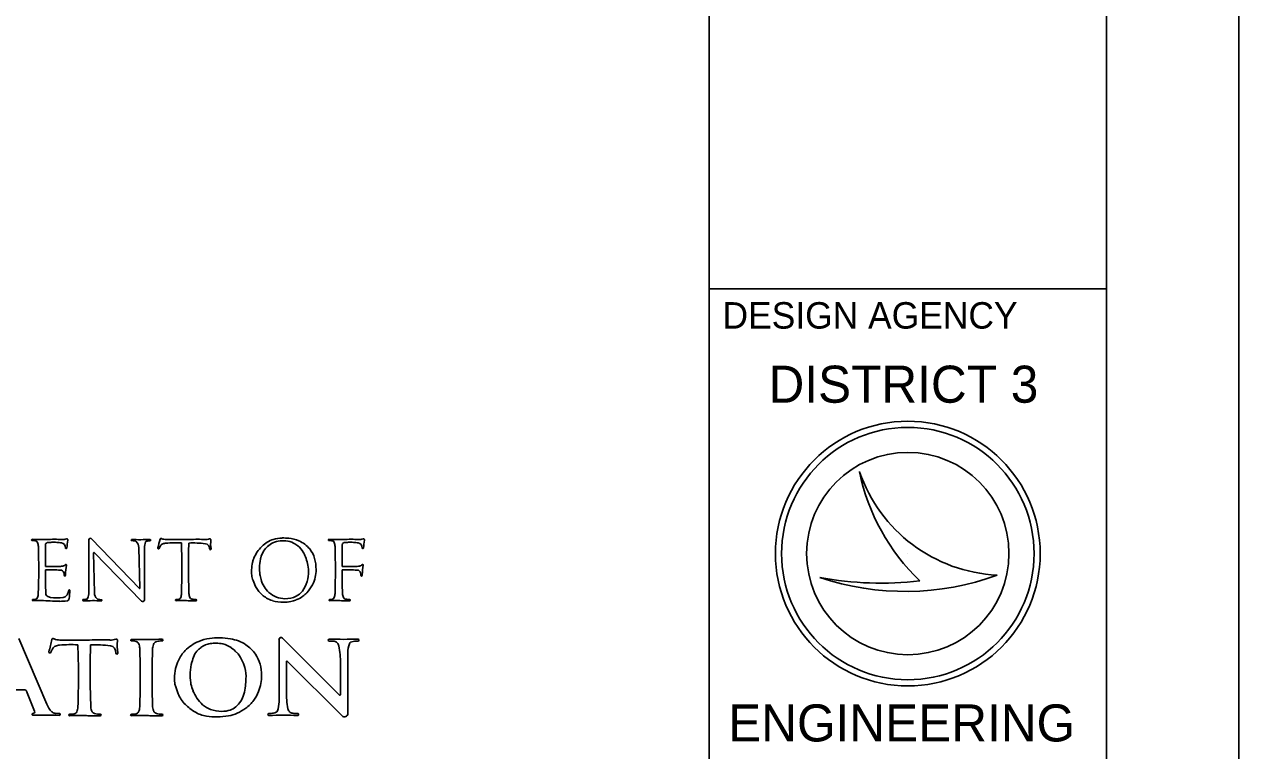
# Model space of a CAD drawing. Extents: x 0 to 34, y 0 to 22.
# Drawn here: x 29.412 to 34, y 2.755 to 5.5 of the extents above; entities that cross this region are included whole.
import ezdxf

# ---------------------------------------------------------------- set-up
doc = ezdxf.new("R2010")
doc.units = 0
for name, color, linetype in [('SH_Border', 7, 'Continuous'), ('SH_Cut_Line', 7, 'Continuous'), ('SH_Data', 7, 'Continuous')]:
    doc.layers.add(name, color=color, linetype=linetype)

msp = doc.modelspace()

# ---------------------------------------------------------------- linework, layer by layer
at = {"layer": 'SH_Border'}
for p, q in [((32, 0.5), (32, 21.5)), ((32, 4.5), (33.5, 4.5))]:
    msp.add_line(p, q, dxfattribs=at)
msp.add_lwpolyline([(1.5, 21.5), (33.5, 21.5), (33.5, 0.5), (1.5, 0.5)], close=True, dxfattribs=at)
at = {"layer": 'SH_Cut_Line'}
msp.add_lwpolyline([(0, 0), (34, 0), (34, 22), (0, 22)], close=True, dxfattribs=at)
at = {"layer": 'SH_Data'}
for p, q in [((32.5674, 3.8096), (32.5675, 3.8096)), ((29.6564, 3.5518), (29.6564, 3.3539)), ((29.8471, 3.3685), (29.6667, 3.556)), ((29.6772, 3.3511), (29.6739, 3.5024)), ((29.6768, 3.5036), (29.8551, 3.3207)), ((29.8452, 3.5235), (29.8486, 3.3691)), ((29.866, 3.3251), (29.866, 3.5207)), ((32.75, 3.5), (32.75, 3.5)), ((30.0328, 3.4513), (30.0328, 3.4389)), ((30.2785, 3.4793), (30.2785, 3.4793)), ((32.4172, 3.4095), (32.4172, 3.4095)), ((33.0873, 3.4185), (33.0873, 3.4185)), ((29.4971, 2.9305), (29.3913, 3.1796)), ((30.3746, 2.9394), (30.3746, 3.1752)), ((30.3883, 3.1809), (30.6031, 2.9655)), ((30.6348, 3.1256), (30.6348, 2.8959)), ((30.4025, 3.0919), (30.4025, 2.9795)), ((30.6129, 2.8867), (30.4049, 3.0929)), ((30.6069, 2.9671), (30.6069, 3.0855)), ((29.6614, 3.032), (29.6613, 3.0474)), ((29.327, 2.9848), (29.4146, 2.9848)), ((29.4213, 2.9802), (29.4512, 2.9046)), ((29.4971, 2.9305), (29.4971, 2.9305))]:
    msp.add_line(p, q, dxfattribs=at)
for radius in [0.5, 0.4768, 0.4768, 0.3822]:
    msp.add_circle((32.75, 3.5), radius, dxfattribs=at)
for centre, radius, start, end in [((33.1159, 3.9976), 0.5798, 198.9257, 198.9319), ((33.3467, 3.9701), 0.7956, 191.6379, 191.6421), ((33.1159, 3.9976), 0.5798, 198.9319, 267.1657), ((33.3467, 3.9701), 0.7956, 191.6421, 226.0947), ((29.4422, 3.5516), 0.00228, 85.6429, 267.986), ((29.4459, 3.656), 0.1067, 267.986, 269.6056), ((29.4756, 3.989), 0.4363, 265.6429, 272.4818), ((29.4441, 3.388), 0.1612, 87.8585, 89.6056), ((29.4493, 3.5274), 0.0217, 70.7604, 87.8585), ((29.4531, 3.5383), 0.0102, 19.7623, 70.7604), ((29.4164, 3.5252), 0.0491, 1.7776, 19.7623), ((33.3002, 3.4574), 3.8083, 178.862, 180.092), ((29.5017, 3.5329), 0.00901, 166.7992, 178.862), ((29.5017, 3.5329), 0.00901, 94.329, 166.7992), ((29.5389, 2.5267), 1.0273, 90.6415, 92.4818), ((29.5277, 3.1898), 0.353, 91.9186, 94.329), ((29.5212, 3.3842), 0.1586, 84.8974, 91.9186), ((29.5318, 3.1609), 0.393, 86.7596, 90.6415), ((29.4913, 3.049), 0.4951, 82.8496, 84.8974), ((29.5508, 3.5234), 0.0169, 354.4676, 82.8496), ((29.5568, 3.6018), 0.0485, 266.7596, 287.419), ((29.5726, 3.5515), 0.00418, 350.1932, 107.419), ((29.8747, 3.4993), 0.3024, 170.1932, 175.8069), ((29.6624, 3.5518), 0.00603, 43.8796, 180), ((29.8185, 3.551), 0.00205, 88.0144, 271.2216), ((29.8473, 4.3838), 0.8313, 268.0144, 272.7235), ((29.8196, 3.4957), 0.0533, 76.384, 91.2216), ((29.8306, 3.5409), 0.00669, 47.2331, 76.384), ((29.8139, 3.5228), 0.0313, 1.2424, 47.2331), ((29.9279, 3.5207), 0.0619, 157.8419, 180), ((29.8744, 3.5425), 0.00413, 102.9109, 157.8419), ((29.886, 3.4917), 0.0562, 89.1136, 102.9109), ((29.887, 3.5507), 0.00275, 269.1136, 92.7235), ((29.3536, 3.6832), 0.5858, 343.9543, 347.2977), ((29.9287, 3.5536), 0.00377, 57.0565, 167.2977), ((29.9404, 3.5222), 0.0153, 108.5195, 152.483), ((29.934, 3.5618), 0.00594, 237.0565, 249.7887), ((29.9486, 3.6015), 0.0483, 249.7887, 269.4589), ((29.9522, 3.4869), 0.0526, 94.677, 108.5195), ((29.9826, 3.1164), 0.4242, 86.8419, 94.677), ((30.0583, 15.2102), 11.6575, 269.45892, 269.81615), ((27.0502, 3.4406), 2.9574, 358.2224, 1.9263), ((30.0219, 3.8621), 0.3094, 269.8161, 272.4818), ((33.841, 3.4574), 3.8083, 178.7595, 180.092), ((30.0477, 3.1059), 0.4342, 83.5706, 91.8541), ((30.0797, 2.5267), 1.0273, 90.6415, 92.4818), ((30.0726, 3.1609), 0.393, 86.7596, 90.6415), ((30.0976, 3.6018), 0.0485, 266.7596, 287.419), ((30.0943, 3.5193), 0.0181, 355.2971, 83.5706), ((30.1134, 3.5515), 0.00418, 350.1932, 107.419), ((30.2036, 3.5359), 0.0873, 170.1932, 191.6899), ((30.3853, 3.4522), 0.1064, 107.613, 135.2994), ((30.3905, 3.4621), 0.0876, 116.7026, 147.5385), ((30.3836, 3.4758), 0.0723, 93.5922, 116.7026), ((30.3871, 3.4465), 0.1123, 90.0889, 107.613), ((30.3923, 3.3371), 0.2112, 87.6816, 93.5922), ((30.3874, 3.2473), 0.3116, 85.6243, 90.0889), ((30.3983, 3.4858), 0.0624, 59.809, 87.6816), ((30.4023, 3.4428), 0.1155, 65.7405, 85.6243), ((30.3574, 3.4156), 0.1436, 52.0865, 59.809), ((30.4022, 3.4424), 0.1159, 40.354, 65.7405), ((30.5631, 3.5516), 0.00228, 85.6429, 267.986), ((30.5667, 3.656), 0.1067, 267.986, 269.6056), ((30.5964, 3.989), 0.4363, 265.6429, 272.4818), ((30.5649, 3.388), 0.1612, 87.8585, 89.6056), ((30.5701, 3.5274), 0.0217, 70.7604, 87.8585), ((30.5739, 3.5383), 0.0102, 19.7623, 70.7604), ((30.5373, 3.5252), 0.0491, 1.7776, 19.7623), ((34.4211, 3.4574), 3.8083, 178.862, 180.092), ((30.6226, 3.5329), 0.00901, 166.7992, 178.862), ((30.6226, 3.5329), 0.00901, 94.329, 166.7992), ((30.6598, 2.5267), 1.0273, 90.6415, 92.4818), ((30.6485, 3.1898), 0.353, 91.9186, 94.329), ((30.642, 3.3842), 0.1586, 84.8974, 91.9186), ((30.6527, 3.1609), 0.393, 86.7596, 90.6415), ((30.6121, 3.049), 0.4951, 82.8496, 84.8974), ((30.6716, 3.5234), 0.0169, 354.4676, 82.8496), ((30.6776, 3.6018), 0.0485, 266.7596, 287.419), ((30.6934, 3.5515), 0.00418, 350.1932, 107.419), ((30.9955, 3.4993), 0.3024, 170.1932, 175.8069), ((26.5094, 3.4406), 2.9574, 358.2224, 1.6678), ((29.5704, 3.5215), 0.00275, 174.4676, 355.814), ((29.6756, 3.5024), 0.0017, 44.2691, 181.2424), ((29.9193, 3.5205), 0.00285, 163.9543, 334.4116), ((30.2207, 3.3762), 0.3313, 152.483, 154.4116), ((30.1152, 3.5176), 0.00287, 175.2971, 11.6899), ((30.4107, 3.4271), 0.1421, 135.2994, 157.2066), ((30.3905, 3.4621), 0.0876, 147.5385, 165.5071), ((30.3959, 3.4649), 0.0811, 29.7562, 52.0865), ((30.3647, 3.4471), 0.117, 20.2973, 29.7562), ((30.2623, 3.4092), 0.2262, 13.7527, 20.2973), ((30.4217, 3.459), 0.0903, 14.436, 40.354), ((27.6302, 3.4406), 2.9574, 358.2224, 1.6678), ((30.6912, 3.5215), 0.00275, 174.4676, 355.814), ((29.3907, 66.5112), 63.0599, 270.092005, 270.136322), ((29.5404, 3.5952), 0.1438, 270.1363, 276.9085), ((29.5559, 3.4673), 0.0149, 276.9085, 321.2725), ((29.5695, 3.4564), 0.0025, 349.4309, 141.2725), ((29.7986, 3.4136), 0.2305, 169.4309, 178.1882), ((30.4432, 3.4297), 0.1726, 167.8164, 176.8679), ((30.3566, 3.4484), 0.084, 158.442, 167.8164), ((30.4107, 3.4271), 0.1421, 157.2066, 158.442), ((30.4206, 3.4436), 0.1201, 178.2857, 190.5998), ((30.4749, 3.442), 0.1744, 167.8795, 178.2857), ((30.4342, 3.4508), 0.1328, 165.5071, 167.8795), ((30.351, 3.4309), 0.1349, 1.1426, 13.7527), ((30.34, 3.438), 0.1747, 0.6253, 14.436), ((30.5116, 66.5112), 63.0599, 270.092005, 270.136322), ((30.6612, 3.5952), 0.1438, 270.1363, 276.9085), ((30.6767, 3.4673), 0.0149, 276.9085, 321.2725), ((30.6903, 3.4564), 0.0025, 349.4309, 141.2725), ((30.9194, 3.4136), 0.2305, 169.4309, 178.1882), ((33.3002, 3.4574), 3.8083, 180.2792, 181.6334), ((29.4966, 2.3819), 1.057, 87.1452, 90.2477), ((29.5485, 3.4236), 0.014, 16.8614, 87.1452), ((29.5273, 3.4172), 0.0362, 359.2549, 16.8614), ((29.5654, 3.4167), 0.00196, 179.2549, 340.6106), ((29.5519, 3.4214), 0.0163, 340.6106, 358.1882), ((33.841, 3.4574), 3.8083, 180.2792, 181.6334), ((30.3827, 3.433), 0.1119, 176.8679, 187.4835), ((30.3677, 3.4311), 0.0968, 187.4835, 199.5864), ((30.4504, 3.4605), 0.1846, 199.5864, 208.6065), ((30.5858, 3.4745), 0.2882, 190.5998, 194.5022), ((30.4039, 3.4275), 0.1003, 194.5022, 227.8932), ((30.3516, 3.4309), 0.1342, 344.2873, 1.1426), ((30.3907, 3.4385), 0.124, 333.1433, 0.6253), ((30.6174, 2.3819), 1.057, 87.1452, 90.2477), ((34.4211, 3.4574), 3.8083, 180.2792, 181.6334), ((30.6694, 3.4236), 0.014, 16.8614, 87.1452), ((30.6481, 3.4172), 0.0362, 359.2549, 16.8614), ((30.6863, 3.4167), 0.00196, 179.2549, 340.6106), ((30.6727, 3.4214), 0.0163, 340.6106, 358.1882), ((32.7394, 4.37), 1.0131, 251.4576, 290.0832), ((32.648, 4.6543), 1.2661, 259.4964, 259.4995), ((32.7394, 4.37), 1.0131, 251.4527, 251.4576), ((32.648, 4.6543), 1.2661, 259.4995, 276.6672), ((29.542, 3.3662), 0.039, 320.8407, 340.269), ((29.5433, 3.3658), 0.0376, 340.269, 352.7536), ((29.5827, 3.3608), 0.00209, 355.1286, 172.7536), ((28.9061, 3.4184), 0.6812, 352.6026, 355.1286), ((29.5944, 3.3539), 0.0619, 337.8419, 0), ((29.7085, 3.3518), 0.0313, 181.2424, 227.2331), ((29.8477, 3.3691), 0.00087, 223.8796, 1.2424), ((30.376, 3.4199), 0.0999, 208.6065, 229.3453), ((30.3988, 3.4218), 0.0926, 227.8932, 268.7516), ((30.4105, 3.3974), 0.0654, 296.3448, 323.2967), ((30.3739, 3.4247), 0.1111, 323.2967, 344.2873), ((30.4013, 3.4254), 0.1076, 306.2827, 316.7511), ((30.3833, 3.4422), 0.1322, 316.7511, 333.1433), ((29.445, 3.3241), 0.00217, 90.3944, 271.2943), ((29.4439, 3.4875), 0.1612, 270.3944, 272.1415), ((29.4706, 2.1905), 1.1317, 89.661, 91.2938), ((29.4491, 3.3481), 0.0217, 272.1415, 289.2396), ((29.4529, 3.3372), 0.0102, 289.2396, 340.2377), ((29.4163, 3.3504), 0.0491, 340.2377, 358.2224), ((29.4746, 2.861), 0.4612, 85.604, 89.661), ((29.5058, 3.3492), 0.0123, 181.6334, 198.7573), ((29.5058, 3.3492), 0.0123, 198.7573, 233.0825), ((29.5148, 3.3612), 0.0272, 233.0825, 262.3896), ((29.5451, 3.7785), 0.4589, 265.604, 270.141), ((29.5343, 3.5075), 0.1748, 262.3896, 278.3614), ((29.5456, 3.5998), 0.2803, 270.141, 275.8096), ((29.5569, 3.3542), 0.0199, 278.3614, 320.8407), ((29.5732, 3.328), 0.00707, 275.8096, 326.4436), ((29.5661, 3.3327), 0.0156, 326.4436, 352.6026), ((29.6354, 3.3239), 0.00275, 89.1136, 272.7235), ((29.6363, 3.3829), 0.0562, 269.1136, 282.9109), ((29.675, 2.4908), 0.8313, 88.0144, 92.7235), ((29.648, 3.3321), 0.00413, 282.9109, 337.8419), ((29.6918, 3.3337), 0.00669, 227.2331, 256.384), ((29.7027, 3.379), 0.0533, 256.384, 271.2216), ((29.7039, 3.3237), 0.00205, 268.0144, 91.2216), ((29.8597, 3.3251), 0.00635, 224.2691, 0), ((29.9858, 3.3241), 0.00217, 90.3944, 271.2943), ((29.9847, 3.4875), 0.1612, 270.3944, 272.1415), ((30.0114, 2.1905), 1.1317, 89.661, 91.2938), ((29.9899, 3.3481), 0.0217, 272.1415, 289.2396), ((29.9937, 3.3372), 0.0102, 289.2396, 340.2377), ((29.9571, 3.3504), 0.0491, 340.2377, 358.2224), ((30.0154, 2.861), 0.4612, 88.0337, 89.661), ((30.0624, 4.2315), 0.9101, 268.0337, 269.9476), ((30.0727, 3.35), 0.0384, 181.6334, 205.2525), ((30.0469, 3.3378), 0.00988, 205.2525, 258.54), ((30.0624, 3.4141), 0.0877, 258.54, 269.5198), ((30.0616, 3.3239), 0.00247, 269.9476, 89.5198), ((30.4028, 3.4511), 0.141, 229.3453, 237.7571), ((30.3724, 3.403), 0.0841, 237.7571, 254.2366), ((30.3943, 3.4805), 0.1647, 254.2366, 269.1033), ((30.3935, 3.4269), 0.111, 269.1033, 283.3048), ((30.3987, 3.4212), 0.092, 268.7516, 296.3448), ((30.3765, 3.4985), 0.1847, 283.3048, 289.5494), ((30.4037, 3.4221), 0.1035, 289.5494, 306.2827), ((30.5659, 3.3241), 0.00217, 90.3944, 271.2943), ((30.5647, 3.4875), 0.1612, 270.3944, 272.1415), ((30.5915, 2.1905), 1.1317, 89.661, 91.2938), ((30.5699, 3.3481), 0.0217, 272.1415, 289.2396), ((30.5738, 3.3372), 0.0102, 289.2396, 340.2377), ((30.5371, 3.3504), 0.0491, 340.2377, 358.2224), ((30.5954, 2.861), 0.4612, 88.0337, 89.661), ((30.6425, 4.2315), 0.9101, 268.0337, 269.9476), ((30.6527, 3.35), 0.0384, 181.6334, 205.2525), ((30.627, 3.3378), 0.00988, 205.2525, 258.54), ((30.6424, 3.4141), 0.0877, 258.54, 269.5198), ((30.6417, 3.3239), 0.00247, 269.9476, 89.5198), ((29.915, 3.1531), 0.0145, 103.8002, 151.1101), ((29.9332, 3.0792), 0.0907, 90.3916, 103.8002), ((30.1322, 3.0238), 0.1566, 112.9649, 135.6712), ((30.1324, 3.0233), 0.1571, 97.4106, 112.9649), ((30.1498, 2.8893), 0.2923, 89.8642, 97.4106), ((30.1499, 2.9337), 0.2479, 80.3576, 89.8642), ((30.1658, 3.027), 0.1532, 57.0392, 80.3576), ((30.3826, 3.1752), 0.00808, 44.9226, 180), ((30.565, 3.1729), 0.00418, 87.2578, 273.9158), ((30.6187, 4.2931), 1.1172, 267.2578, 272.7422), ((30.5729, 3.0587), 0.1104, 84.7112, 93.9158), ((30.5813, 3.1498), 0.0188, 44.6622, 84.7112), ((30.6573, 3.1447), 0.0235, 94.7322, 121.0781), ((30.6734, 2.9502), 0.2187, 90.2807, 94.7322), ((30.6723, 3.173), 0.00413, 270.2807, 92.7422), ((30.1026, 3.049), 0.1179, 134.4003, 156.2497), ((30.1111, 3.09), 0.0623, 132.3383, 156.723), ((30.2177, 2.973), 0.2206, 128.9973, 132.3383), ((30.1256, 3.0868), 0.0742, 113.2653, 128.9973), ((30.124, 3.0905), 0.0702, 97.5949, 113.2653), ((30.1343, 3.0132), 0.1482, 88.9186, 97.5949), ((30.1345, 3.0213), 0.1401, 78.3422, 88.9186), ((30.1467, 3.0807), 0.0794, 53.4218, 78.3422), ((30.0867, 2.9997), 0.1802, 44.8554, 53.4218), ((30.1445, 3.0572), 0.0987, 25.6751, 44.8554), ((30.1802, 3.0493), 0.1267, 33.5981, 57.0392), ((30.5786, 3.1471), 0.0226, 10.4886, 44.6622), ((30.2459, 3.0855), 0.361, 0, 10.4886), ((30.7336, 3.1256), 0.0988, 160.0072, 180), ((30.6506, 3.1558), 0.0105, 121.0781, 160.0072), ((30.1654, 3.0213), 0.1865, 156.2497, 166.3115), ((30.2359, 3.0401), 0.1969, 165.298, 188.4367), ((30.2137, 3.0459), 0.1739, 156.723, 165.298), ((30.0509, 3.0123), 0.2025, 16.2741, 25.6751), ((30.1706, 3.0429), 0.1382, 16.3589, 33.5981), ((30.1647, 3.0412), 0.1443, 359.3686, 16.3589), ((30.4039, 3.0919), 0.00143, 45.2517, 180), ((30.1484, 3.0255), 0.169, 166.3115, 178.9602), ((30.082, 3.0267), 0.1026, 178.9602, 191.4231), ((30.1289, 3.035), 0.1212, 355.9908, 16.2741), ((30.1347, 3.0415), 0.1743, 338.9088, 359.3686), ((29.4146, 2.9775), 0.00726, 21.558, 90), ((30.0301, 3.0162), 0.0497, 191.4231, 198.9072), ((30.763, 3.2672), 0.8244, 198.9072, 201.1049), ((30.1015, 3.0201), 0.0611, 188.4367, 192.5352), ((30.1992, 3.0419), 0.1611, 192.5352, 201.9074), ((30.1056, 3.0105), 0.1428, 342.8783, 355.7772), ((23.1348, 3.5252), 7.1325, 355.7772, 355.99084), ((30.1011, 3.0118), 0.1149, 201.1049, 225.6248), ((30.1906, 3.0384), 0.1519, 201.9074, 213.7201), ((30.176, 3.0286), 0.1343, 213.7201, 228.0048), ((30.1523, 2.9907), 0.0915, 310.4099, 327.9455), ((30.1352, 3.0014), 0.1118, 327.9455, 342.8783), ((30.1687, 3.0269), 0.1372, 305.7618, 323.6649), ((30.1646, 3.03), 0.1423, 323.6649, 338.9088), ((30.2758, 2.9394), 0.0988, 340.0072, 0), ((30.7634, 2.9795), 0.361, 180, 190.4886), ((30.6047, 2.9671), 0.0022, 224.9226, 0), ((29.445, 2.8924), 0.0034, 89.2063, 271.9867), ((29.4452, 2.9023), 0.00647, 269.2063, 21.558), ((29.5788, 2.9652), 0.0887, 203.0123, 225.1414), ((29.5301, 2.9163), 0.0197, 225.1414, 263.7877), ((29.5395, 3.0025), 0.1065, 263.7877, 272.4172), ((29.5442, 2.8924), 0.00377, 267.5828, 92.4172), ((29.6814, 2.9096), 0.0145, 208.8899, 256.1998), ((29.6996, 2.9836), 0.0907, 256.1998, 269.6084), ((29.915, 2.9096), 0.0145, 208.8899, 256.1998), ((29.9332, 2.9836), 0.0907, 256.1998, 269.6084), ((30.1613, 3.0732), 0.2009, 225.6248, 238.5006), ((30.1183, 3.0031), 0.1186, 238.5006, 261.7093), ((30.1467, 2.9962), 0.0906, 228.0048, 250.0405), ((30.1574, 3.0256), 0.122, 250.0405, 270.4703), ((30.1576, 3.0083), 0.1046, 270.4703, 287.9615), ((30.1621, 3.0165), 0.1314, 279.5268, 294.5661), ((30.17, 2.9699), 0.0643, 287.9615, 310.4099), ((30.1376, 3.0702), 0.1905, 294.5661, 305.7618), ((30.337, 2.892), 0.00413, 90.2807, 272.7422), ((30.3359, 3.1148), 0.2187, 270.2807, 274.7322), ((30.352, 2.9203), 0.0235, 274.7322, 301.0781), ((30.3587, 2.9092), 0.0105, 301.0781, 340.0072), ((30.4307, 2.9179), 0.0226, 190.4886, 224.6622), ((30.4281, 2.9152), 0.0188, 224.6622, 264.7112), ((30.4365, 3.0064), 0.1104, 264.7112, 273.9158), ((30.4443, 2.8921), 0.00418, 267.2578, 93.9158), ((30.6219, 2.8959), 0.0129, 225.2517, 0), ((29.4898, 1.6033), 1.2865, 87.5828, 91.9867), ((30.1381, 3.1389), 0.2559, 261.7093, 270.7387), ((30.1378, 3.1617), 0.2787, 270.7387, 279.5268), ((30.3907, 1.772), 1.1172, 87.2578, 92.7422)]:
    msp.add_arc(centre, radius, start, end, dxfattribs=at)
for centre, major_axis, ratio, start_param, end_param in [((28.7785, 3.353), (-0.005, 0.8081), 0.935925, 4.426098, 4.484451), ((29.5212, 3.1739), (-0.00003, 0.0052), 0.935925, 5.701972, 7.626044), ((29.528, 3.1851), (-0.00005, 0.0082), 0.935925, 2.560379, 2.782597), ((29.5469, 3.2399), (-0.0004, 0.0666), 0.935925, 2.782597, 3.125908), ((29.682, 19.2559), (-0.1004, 16.0831), 0.935925, 3.125908, 3.132143), ((29.6413, 3.5995), (-0.0027, 0.4268), 0.935925, 3.132143, 3.178667), ((29.7167, 1.757), (-0.0088, 1.4173), 0.935925, 0.004955, 0.037075), ((29.7072, 2.632), (-0.0034, 0.5423), 0.935925, 6.220389, 6.28814), ((29.7392, 3.2403), (-0.0004, 0.067), 0.935925, 3.078796, 3.439371), ((29.7596, 3.1709), (0.00004, -0.00577), 0.935925, 1.393395, 3.439371), ((29.8761, 3.1493), (-0.0008, 0.1205), 0.935925, 1.393395, 1.768582), ((29.8175, 3.1726), (0.00329, 0), 0.815575, 1.548207, 4.705505), ((29.8158, 2.9705), (-0.2446, 0), 0.815575, 4.675013, 4.705505), ((29.8564, 4.5752), (1.7169, 0), 0.815575, 4.689808, 4.718306), ((29.8237, 3.1429), (0.033, 0), 0.815575, 1.235003, 1.53342), ((29.8295, 3.1564), (0.0155, 0), 0.815575, 0.344917, 1.235003), ((29.8624, 3.7456), (0.6997, 0), 0.815575, 4.718306, 4.746708), ((29.9338, 2.05), (1.3806, 0), 0.815575, 1.57171, 1.605116), ((29.9325, 3.1729), (0.00375, 0), 0.815575, 4.720769, 7.854895), ((29.509, 3.1283), (-0.00002, 0.00393), 0.935925, 1.284505, 4.259546), ((29.8982, 2.929), (-0.0029, 0.457), 0.935925, 1.084293, 1.117953), ((29.5363, 3.1306), (-0.0001, 0.0211), 0.935925, 0.316985, 1.084293), ((29.5516, 3.0818), (-0.0005, 0.0725), 0.935925, 0.075388, 0.316985), ((29.5909, 2.5707), (-0.0037, 0.5853), 0.935925, 6.233364, 6.358573), ((25.1303, 3.0342), (4.4867, 0), 0.815575, 6.25216, 6.316325), ((35.4387, 3.055), (5.7774, 0), 0.815575, 3.120359, 3.143198), ((29.6751, 2.5562), (-0.0037, 0.599), 0.935925, 6.16473, 6.298779), ((29.735, 3.1265), (-0.0002, 0.025), 0.935925, 4.624066, 6.16473), ((29.762, 3.1241), (-0.00002, 0.00396), 0.935925, 1.482474, 4.910175), ((29.7739, 3.1401), (0.0746, 0), 0.815575, 0.031026, 0.344917), ((25.3639, 3.0285), (4.4867, 0), 0.815575, 0.000778, 0.031026), ((35.6723, 3.0077), (5.7774, 0), 0.815575, 3.113084, 3.136574), ((29.9554, 3.1407), (-0.0582, 0), 0.815575, 5.860303, 6.254677), ((35.4387, 3.055), (5.7774, 0), 0.815575, 3.146466, 3.170101), ((25.3639, 3.0342), (4.4867, 0), 0.815575, 6.25216, 6.282407), ((35.6723, 3.055), (5.7774, 0), 0.815575, 3.146611, 3.170101), ((29.584, 2.8901), (0.00329, 0), 0.815575, 1.57768, 4.734978), ((29.5823, 3.0923), (-0.2446, 0), 0.815575, 1.57768, 1.608173), ((29.5902, 2.9198), (-0.033, 0), 0.815575, 1.608173, 1.90659), ((29.596, 2.9063), (0.0155, 0), 0.815575, 5.048183, 5.938269), ((29.5403, 2.9226), (0.0746, 0), 0.815575, 5.938269, 6.25216), ((29.7218, 2.922), (-0.0582, 0), 0.815575, 0.028508, 0.422883), ((29.699, 2.8898), (0.00375, 0), 0.815575, 4.711475, 7.845601), ((29.8175, 2.8901), (0.00329, 0), 0.815575, 1.57768, 4.734978), ((29.8158, 3.0923), (-0.2446, 0), 0.815575, 1.57768, 1.608173), ((29.8237, 2.9198), (-0.033, 0), 0.815575, 1.608173, 1.90659), ((29.8295, 2.9063), (0.0155, 0), 0.815575, 5.048183, 5.938269), ((29.7739, 2.9226), (0.0746, 0), 0.815575, 5.938269, 6.25216), ((29.9554, 2.922), (-0.0582, 0), 0.815575, 0.028508, 0.422883), ((29.9325, 2.8898), (0.00375, 0), 0.815575, 4.711475, 7.845601), ((29.6228, 1.4875), (1.7169, 0), 0.815575, 1.564879, 1.593377), ((29.6288, 2.3171), (0.6997, 0), 0.815575, 1.536477, 1.564879), ((29.7002, 4.0127), (1.3806, 0), 0.815575, 4.67807, 4.711475), ((29.8564, 1.4875), (1.7169, 0), 0.815575, 1.564879, 1.593377), ((29.8624, 2.3171), (0.6997, 0), 0.815575, 1.536477, 1.564879), ((29.9338, 4.0127), (1.3806, 0), 0.815575, 4.67807, 4.711475)]:
    msp.add_ellipse(centre, major_axis=major_axis, ratio=ratio, start_param=start_param, end_param=end_param, dxfattribs=at)

# ---------------------------------------------------------------- texts
for s, height, p in [('DESIGN AGENCY', 0.1, (32.05, 4.35)), ('DISTRICT 3', 0.14, (32.2237, 4.07)), ('ENGINEERING', 0.14, (32.0713, 2.79))]:
    msp.add_text(s, height=height, dxfattribs=at).set_placement(p)

doc.saveas('drawing.dxf')
